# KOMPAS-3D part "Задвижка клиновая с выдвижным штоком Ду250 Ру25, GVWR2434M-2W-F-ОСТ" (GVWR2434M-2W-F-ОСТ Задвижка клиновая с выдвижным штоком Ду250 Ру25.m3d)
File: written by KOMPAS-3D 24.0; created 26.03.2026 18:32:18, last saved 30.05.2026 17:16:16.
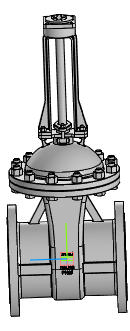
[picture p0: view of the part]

Document properties: Автор: R2D2; Полное имя файла: E:\Работа\Зайцев\GVWR2434M-2W-F-ОСТ Задвижка клиновая с выдвижным штоком DN.ru Ду50-300 Ру25\исходные материалы\DN250\DN250\GVWR2434M-2W-F-ОСТ Задвижка клиновая с выдвижным штоком Ду250 Ру25.m3d

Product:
- Part/product: Задвижка клиновая с выдвижным штоком Ду250 Ру25  | designation GVWR2434M-2W-F-ОСТ
    Масса: 175
    Раздел спецификации: Прочие изделия
    Примечание: D040-07591

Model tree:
1. Операция без истории:1

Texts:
  GVWR2434M-2W-F-ОСТ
